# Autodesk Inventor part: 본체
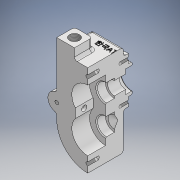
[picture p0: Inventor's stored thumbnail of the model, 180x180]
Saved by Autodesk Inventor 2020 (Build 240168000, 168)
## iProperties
Created: 2024-03
Part Number: 본체
Material: 일반
Document SubType Name: Modeling
Designer: 1강의실14
Density: 1 g/cm^3
Appearance: 기본값
Author: 1강의실14
## Parameters: d4 = 35 mm, d5 = 12 mm, d7 = 0, d9 = 12 mm, d11 = 0, d12 = 0, d14 = 8 mm, d15 = 25 mm, d16 = 63.5 mm, d18 = 6 mm, d19 = 0, d20 = 0, d21 = 10.5 mm, d22 = 11 mm, d23 = 0.62479 mm, d24 = 10.589 mm, d25 = 4 mm, d26 = 2 mm, d27 = 90 deg, d28 = 16 mm, d29 = 118 deg, d30 = 36 mm, d31 = 36 mm, d32 = 33 mm, d33 = 28 mm, d35 = 0, d37 = 11 mm, d38 = 4 mm, d39 = 2 mm, d40 = 90 deg, d42 = 0, d43 = 14 mm, d44 = 120 deg, d45 = 90 deg, d46 = 26 mm, d47 = 59 mm, d48 = 4.134 mm, d50 = 4 mm, d51 = 2 mm, d52 = 90 deg, d53 = 12 mm, d54 = 118 deg, d55 = 15 mm, d57 = 4 mm, d58 = 2 mm, d59 = 90 deg, d60 = 12 mm, d61 = 118 deg, d62 = 32 mm, d64 = 0, d65 = 52 mm, d66 = 6 mm, d67 = 0, d68 = 0.7 mm, d69 = 2 mm, d70 = 30 deg, d71 = 42 mm, d72 = 35 mm, d73 = 3.242 mm, d74 = 8 mm, d75 = 4 mm, d76 = 2 mm, d77 = 90 deg, d79 = 118 deg, d81 = 360 deg, d83 = 63.5 mm, d86 = 0, d87 = 4.134 mm, d89 = 4 mm, d90 = 2 mm, d91 = 90 deg, d92 = 12 mm, d93 = 118 deg, d94 = 3 mm, d95 = 1 mm, d96 = 2 mm, d97 = 45 deg, d98 = 1 mm, d99 = 2 mm, d100 = 45 deg, d101 = 1 mm, d102 = 2 mm, d103 = 45 deg, d105 = 0.5 mm, d106 = 0, d107 = 25 mm, d110 = 2 mm, d111 = 90 deg, d112 = 7.3 mm, d113 = 0, d114 = 0.7 mm, d115 = 2 mm, d116 = 30 deg
